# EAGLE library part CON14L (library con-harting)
CONNECTOR
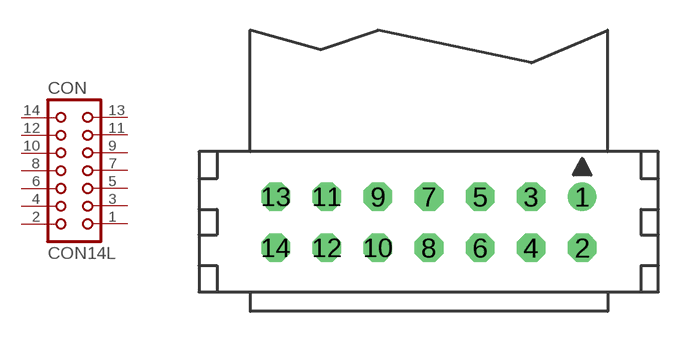
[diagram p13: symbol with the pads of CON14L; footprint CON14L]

Designator prefix CON

## CON14L (OC_FARNELL: unknown; OC_NEWARK: unknown)  [CON14L]
1  1  pas
2  2  pas
3  3  pas
4  4  pas
5  5  pas
6  6  pas
7  7  pas
8  8  pas
9  9  pas
10  10  pas
11  11  pas
12  12  pas
13  13  pas
14  14  pas

## Footprint CON14L (pad centres in mm)
CONNECTOR
drill 0.914 round: 1 7.62,1.27
drill 0.914 octagon: 2 7.62,-1.27; 3 5.08,1.27; 4 5.08,-1.27; 5 2.54,1.27; 6 2.54,-1.27; 7 0,1.27; 8 0,-1.27; 9 -2.54,1.27; 10 -2.54,-1.27; 11 -5.08,1.27; 12 -5.08,-1.27; 13 -7.62,1.27; 14 -7.62,-1.27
